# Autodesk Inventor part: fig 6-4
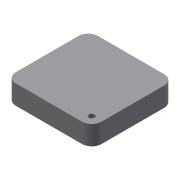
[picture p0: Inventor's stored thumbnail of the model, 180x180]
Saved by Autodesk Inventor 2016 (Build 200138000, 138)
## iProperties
Created: 2004-05
Part Number: fig 6-4
Document SubType Name: Modeling
Designer: CADCIM Technologies
Manufacturer: Standard
Standards Organization: Custom
Density: 1 g/cm^3
Material: Generic
Appearance: Default
Author: CADCIM Technologies
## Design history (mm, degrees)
sketch "Sketch1"
  geometry: L1 (0, 0)-(44.293, 0); L2 (44.293, 0)-(44.293, 42.442); L3 (44.293, 42.442)-(0, 42.442); L4 (0, 42.442)-(0, 0)
  constraints: 8 end point, 2 parallel, 1 horizontal, 1 perpendicular
extrude "Extrusion1" new body sketch "Sketch1" distance "d0" = 10; taper "d1" = 0 deg
fillet "Fillet1" dims "d2" = 5
sketch "Sketch2"
  geometry: 1 further point
sketch "Sketch3"
  geometry: L1 (5, 42.442)-(39.293, 42.442) reference; L2 (0, 5)-(0, 37.442) reference; L3 (39.293, 0)-(5, 0) reference; L4 (44.293, 37.442)-(44.293, 5) reference; A1 r 5 centre (39.293, 37.442) between (44.293, 37.442) and (39.293, 42.442) reference; A2 r 5 centre (5, 37.442) between (5, 42.442) and (0, 37.442) reference; A3 r 5 centre (5, 5) between (0, 5) and (5, 0) reference; A4 r 5 centre (39.293, 5) between (39.293, 0) and (44.293, 5) reference; 1 further point
hole "Hole2" diameter "d15" = 3; stored, may be unused: countersink angle "d19" = 90 deg, drill point angle "d21" = 118 deg; dims "d13" = 10, "d14" = 10, "d16" = 6, "d17" = 4, "d18" = 2, "d20" = 8
body "Solid1"
